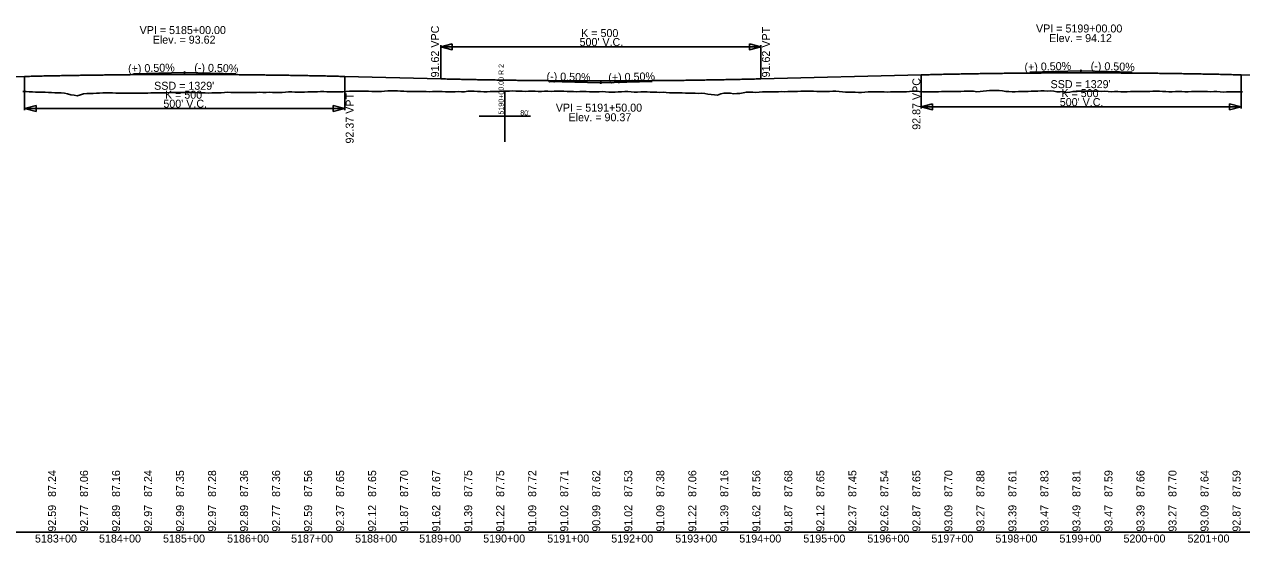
# Model space of a CAD drawing. Extents: x 2147288 to 2220488, y 740833 to 759333.
# Drawn here: x 2150631 to 2152532, y 750067 to 750877 of the extents above; entities that cross this region are included whole.
import ezdxf

# ---------------------------------------------------------------- set-up
doc = ezdxf.new("R2010")
doc.units = 0
for name, color, linetype in [('RD_DDB_GradeTX', 7, 'Continuous'), ('RD_DDB_Profile_EX', 7, 'Continuous'), ('RD_DDB_Profile_Lbl', 7, 'Continuous'), ('RD_DDB_Profile_PR', 7, 'Continuous'), ('RD_DDB_StaTX', 7, 'Continuous'), ('RD_DDB_StripGrade', 7, 'Continuous'), ('RD_DDB_VCLbl', 7, 'Continuous'), ('RD_GPK_Profile_Cell', 7, 'Continuous')]:
    doc.layers.add(name, color=color, linetype=linetype)

msp = doc.modelspace()

# ---------------------------------------------------------------- linework, layer by layer
at = {"layer": 'RD_DDB_GradeTX'}
for p, q in [((2150801.1, 750799.5), (2150880.1, 750801.5)), ((2150961.1, 750799.5), (2150882.1, 750801.5)), ((2152201.1, 750802), (2152280.1, 750804)), ((2152361.1, 750802), (2152282.1, 750804)), ((2151451.1, 750787.3), (2151530.1, 750785.3)), ((2151611.1, 750787.3), (2151532.1, 750785.3))]:
    msp.add_line(p, q, dxfattribs=at)
for centre in [(2150881.1, 750801.5), (2152281.1, 750804), (2151531.1, 750785.3)]:
    msp.add_circle(centre, 1, dxfattribs=at)
at = {"layer": 'RD_DDB_Profile_EX'}
for points in [[(2150628.3, 750771.7), (2150633.3, 750771.6), (2150638.3, 750771.3), (2150643.3, 750771.1), (2150648.3, 750771), (2150653.3, 750770.9), (2150658.3, 750770.7), (2150663.3, 750770.6), (2150668.3, 750770.3), (2150673.3, 750770), (2150678.3, 750769.6), (2150683.3, 750769.7), (2150688.3, 750769.6), (2150693.3, 750769.1), (2150698.3, 750767.9), (2150703.3, 750766.4), (2150708.3, 750765.8), (2150713.3, 750765.1), (2150718.3, 750766.8), (2150723.3, 750768), (2150728.3, 750768.6), (2150733.3, 750768.7), (2150738.3, 750768.9), (2150743.3, 750769.1), (2150748.3, 750769.2), (2150753.3, 750769.5), (2150758.3, 750769.7), (2150763.3, 750769.7), (2150768.3, 750769.6), (2150773.3, 750769.4), (2150778.3, 750769.3), (2150783.3, 750769.2), (2150788.3, 750769.2), (2150793.3, 750769.2), (2150798.3, 750769.3), (2150803.3, 750769.3), (2150808.3, 750769.2), (2150813.3, 750769.4), (2150818.3, 750769.3), (2150823.3, 750769.3), (2150828.3, 750769.5), (2150833.3, 750769.7), (2150838.3, 750769.9), (2150843.3, 750769.8), (2150848.3, 750769.8), (2150853.3, 750769.8), (2150858.3, 750770), (2150863.3, 750770.1), (2150868.3, 750770.2), (2150873.3, 750770.2), (2150878.3, 750770.2), (2150883.3, 750770.2), (2150888.3, 750770.2), (2150893.3, 750770.4), (2150898.3, 750770.1), (2150903.3, 750769.9), (2150908.3, 750769.7), (2150913.3, 750769.5), (2150918.3, 750769.4), (2150923.3, 750769.6), (2150928.3, 750769.9), (2150933.3, 750769.8), (2150938.3, 750769.7), (2150943.3, 750770.2), (2150948.3, 750770.5), (2150953.3, 750770.3), (2150958.3, 750770.3), (2150963.3, 750770.3), (2150968.3, 750770.2), (2150973.3, 750770.2), (2150978.3, 750770.2), (2150983.3, 750770.2), (2150988.3, 750770.3), (2150993.3, 750770.3), (2150998.3, 750770.5), (2151003.3, 750770.2), (2151008.3, 750770.4), (2151013.3, 750770.5), (2151018.3, 750770.4), (2151023.3, 750770.2), (2151028.3, 750770.1), (2151033.3, 750770.3), (2151038.3, 750770.7)], [(2151038.3, 750770.7), (2151043.3, 750771.1), (2151048.3, 750771.3), (2151053.3, 750771), (2151058.3, 750770.7), (2151063.3, 750770.5), (2151068.3, 750770.8), (2151073.3, 750771.1), (2151078.3, 750771.3), (2151083.3, 750771.2), (2151088.3, 750771.4), (2151093.3, 750771.6), (2151098.3, 750771.8), (2151103.3, 750771.5), (2151108.3, 750771.2), (2151113.3, 750771.2), (2151118.3, 750771.2), (2151123.3, 750771.2), (2151128.3, 750771.5), (2151133.3, 750771.8), (2151138.3, 750772.1), (2151143.3, 750772.1), (2151148.3, 750772.2), (2151153.3, 750772.2), (2151158.3, 750772.2), (2151163.3, 750772.2), (2151168.3, 750772.1), (2151173.3, 750771.9), (2151178.3, 750771.7), (2151183.3, 750771.6), (2151188.3, 750771.6), (2151193.3, 750772.2), (2151198.3, 750772.7), (2151203.3, 750772.6), (2151208.3, 750772.6), (2151213.3, 750772.6), (2151218.3, 750772.5), (2151223.3, 750772.3), (2151228.3, 750772), (2151233.3, 750771.9), (2151238.3, 750771.8), (2151243.3, 750771.8), (2151248.3, 750771.7), (2151253.3, 750771.7), (2151258.3, 750771.6), (2151263.3, 750771.5), (2151268.3, 750771.6), (2151273.3, 750771.8), (2151278.3, 750772), (2151283.3, 750771.6), (2151288.3, 750771.3), (2151293.3, 750771.5), (2151298.3, 750771.5), (2151303.3, 750771.3), (2151308.3, 750771.7), (2151313.3, 750771.5), (2151318.3, 750771.3), (2151323.3, 750772.1), (2151328.3, 750772.3), (2151333.3, 750772.1), (2151338.3, 750771.9), (2151343.3, 750771.7), (2151348.3, 750771.5), (2151353.3, 750771.4), (2151358.3, 750771.6), (2151363.3, 750771.7), (2151368.3, 750771.6), (2151373.3, 750771.9), (2151378.3, 750772.2), (2151383.3, 750772.2), (2151388.3, 750772.4), (2151393.3, 750772.6), (2151398.3, 750772.4), (2151403.3, 750772.5), (2151408.3, 750772.3), (2151413.3, 750772), (2151418.3, 750772.1), (2151423.3, 750772.2), (2151428.3, 750772.2), (2151433.3, 750772), (2151438.3, 750772), (2151443.3, 750772.2), (2151448.3, 750772.1), (2151453.3, 750772), (2151458.3, 750772.1), (2151463.3, 750772.1), (2151468.3, 750772.1), (2151473.3, 750772.1), (2151478.3, 750772), (2151483.3, 750771.9), (2151488.3, 750771.7), (2151493.3, 750771.5), (2151498.3, 750771.6), (2151503.3, 750771.7), (2151508.3, 750771.7), (2151513.3, 750771.2), (2151518.3, 750771.4), (2151523.3, 750771.1), (2151528.3, 750771.2), (2151533.3, 750771.8), (2151538.3, 750771.2)], [(2151538.3, 750771.2), (2151543.3, 750770.9), (2151548.3, 750770.9), (2151553.3, 750770.9), (2151558.3, 750771.1), (2151563.3, 750771.5), (2151568.3, 750771.6), (2151573.3, 750771.7), (2151578.3, 750771.2), (2151583.3, 750770.9), (2151588.3, 750771), (2151593.3, 750771.1), (2151598.3, 750771.5), (2151603.3, 750771.1), (2151608.3, 750770.9), (2151613.3, 750770.7), (2151618.3, 750770.5), (2151623.3, 750770.4), (2151628.3, 750770.6), (2151633.3, 750770.1), (2151638.3, 750769.6), (2151643.3, 750769.5), (2151648.3, 750769.6), (2151653.3, 750769.6), (2151658.3, 750769.6), (2151663.3, 750769.3), (2151668.3, 750769.1), (2151673.3, 750769.3), (2151678.3, 750769), (2151683.3, 750768.6), (2151688.3, 750769.2), (2151693.3, 750768.8), (2151698.3, 750767.5), (2151703.3, 750766.9), (2151708.3, 750766.4), (2151713.3, 750766.2), (2151718.3, 750768.4), (2151723.3, 750769.1), (2151728.3, 750769.2), (2151733.3, 750769.2), (2151738.3, 750768.3), (2151743.3, 750768.5), (2151748.3, 750768.9), (2151753.3, 750769.8), (2151758.3, 750770.8), (2151763.3, 750770.7), (2151768.3, 750770.6), (2151773.3, 750770.2), (2151778.3, 750770.9), (2151783.3, 750771.4), (2151788.3, 750771.3), (2151793.3, 750771.3), (2151798.3, 750771.3), (2151803.3, 750771.2), (2151808.3, 750771.2), (2151813.3, 750771.6), (2151818.3, 750771.5), (2151823.3, 750771.7), (2151828.3, 750771.8), (2151833.3, 750771.9), (2151838.3, 750772), (2151843.3, 750772.4), (2151848.3, 750772.3), (2151853.3, 750772.1), (2151858.3, 750772.3), (2151863.3, 750772.1), (2151868.3, 750771.9), (2151873.3, 750771.8), (2151878.3, 750771.6), (2151883.3, 750771.7), (2151888.3, 750771.9), (2151893.3, 750772.1), (2151898.3, 750772.3), (2151903.3, 750771.7), (2151908.3, 750771.1), (2151913.3, 750770.7), (2151918.3, 750770.6), (2151923.3, 750770.9), (2151928.3, 750771), (2151933.3, 750770.4), (2151938.3, 750770.3), (2151943.3, 750770.7), (2151948.3, 750771.1), (2151953.3, 750771.4), (2151958.3, 750771.3), (2151963.3, 750771.3), (2151968.3, 750771.2), (2151973.3, 750771.2), (2151978.3, 750771), (2151983.3, 750771.3), (2151988.3, 750771.1), (2151993.3, 750771.1), (2151998.3, 750771.3), (2152003.3, 750771.5), (2152008.3, 750771.5), (2152013.3, 750771.9), (2152018.3, 750772.5), (2152023.3, 750772.2), (2152028.3, 750771.9), (2152033.3, 750771.5), (2152038.3, 750771.3)], [(2152038.3, 750771.3), (2152043.3, 750771.2), (2152048.3, 750771.3), (2152053.3, 750771.4), (2152058.3, 750771.5), (2152063.3, 750771.6), (2152068.3, 750771.7), (2152073.3, 750771.8), (2152078.3, 750771.9), (2152083.3, 750772), (2152088.3, 750771.9), (2152093.3, 750771.9), (2152098.3, 750772.1), (2152103.3, 750772.4), (2152108.3, 750772.5), (2152113.3, 750772.1), (2152118.3, 750771.5), (2152123.3, 750771.9), (2152128.3, 750772.5), (2152133.3, 750773), (2152138.3, 750773.3), (2152143.3, 750773.6), (2152148.3, 750773.4), (2152153.3, 750773.1), (2152158.3, 750772.8), (2152163.3, 750772), (2152168.3, 750771.6), (2152173.3, 750771.2), (2152178.3, 750771.4), (2152183.3, 750771.6), (2152188.3, 750771.6), (2152193.3, 750771.7), (2152198.3, 750771.8), (2152203.3, 750772.1), (2152208.3, 750772.3), (2152213.3, 750772.3), (2152218.3, 750772.6), (2152223.3, 750772.7), (2152228.3, 750772.5), (2152233.3, 750772.7), (2152238.3, 750772.2), (2152243.3, 750771.3), (2152248.3, 750771.2), (2152253.3, 750771.7), (2152258.3, 750770.4), (2152263.3, 750770.8), (2152268.3, 750771.7), (2152273.3, 750772.1), (2152278.3, 750772.4), (2152283.3, 750772.5), (2152288.3, 750772.3), (2152293.3, 750772.5), (2152298.3, 750772.4), (2152303.3, 750772.4), (2152308.3, 750772.2), (2152313.3, 750772), (2152318.3, 750772.1), (2152323.3, 750771.9), (2152328.3, 750771.2), (2152333.3, 750771.6), (2152338.3, 750772), (2152343.3, 750771.3), (2152348.3, 750771.1), (2152353.3, 750771.5), (2152358.3, 750772), (2152363.3, 750771.8), (2152368.3, 750771.8), (2152373.3, 750771.8), (2152378.3, 750771.6), (2152383.3, 750771.8), (2152388.3, 750772), (2152393.3, 750772.2), (2152398.3, 750772.3), (2152403.3, 750772.3), (2152408.3, 750772), (2152413.3, 750771.7), (2152418.3, 750771.5), (2152423.3, 750771.3), (2152428.3, 750771.8), (2152433.3, 750772), (2152438.3, 750771.7), (2152443.3, 750771.5), (2152448.3, 750771.5), (2152453.3, 750771.6), (2152458.3, 750771.7), (2152463.3, 750771.6), (2152468.3, 750771.8), (2152473.3, 750772), (2152478.3, 750771.7), (2152483.3, 750771.5), (2152488.3, 750771.6), (2152493.3, 750771.6), (2152498.3, 750771.3), (2152503.3, 750771), (2152508.3, 750771.2), (2152513.3, 750771.4), (2152518.3, 750771.5), (2152523.3, 750771.5), (2152528.3, 750771.4), (2152533.3, 750771.3)]]:
    msp.add_lwpolyline(points, dxfattribs=at)
at = {"layer": 'RD_DDB_Profile_PR'}
for p, q in [((2151781.1, 750791.5), (2152031.1, 750797.8)), ((2152531.1, 750797.8), (2152781.1, 750791.5)), ((2150481.1, 750791.5), (2150631.1, 750795.3)), ((2151131.1, 750795.3), (2151281.1, 750791.5))]:
    msp.add_line(p, q, dxfattribs=at)
for points in [[(2150631.1, 750795.3), (2150641.1, 750795.5), (2150651.1, 750795.7), (2150661.1, 750796), (2150671.1, 750796.2), (2150681.1, 750796.4), (2150691.1, 750796.6), (2150701.1, 750796.8), (2150711.1, 750796.9), (2150721.1, 750797.1), (2150731.1, 750797.3), (2150741.1, 750797.4), (2150751.1, 750797.5), (2150761.1, 750797.7), (2150771.1, 750797.8), (2150781.1, 750797.9), (2150791.1, 750798), (2150801.1, 750798.1), (2150811.1, 750798.1), (2150821.1, 750798.2), (2150831.1, 750798.3), (2150841.1, 750798.3), (2150851.1, 750798.3), (2150861.1, 750798.4), (2150871.1, 750798.4), (2150881.1, 750798.4), (2150891.1, 750798.4), (2150901.1, 750798.4), (2150911.1, 750798.3), (2150921.1, 750798.3), (2150931.1, 750798.3), (2150941.1, 750798.2), (2150951.1, 750798.1), (2150961.1, 750798.1), (2150971.1, 750798), (2150981.1, 750797.9), (2150991.1, 750797.8), (2151001.1, 750797.7), (2151011.1, 750797.5), (2151021.1, 750797.4), (2151031.1, 750797.3), (2151041.1, 750797.1), (2151051.1, 750796.9), (2151061.1, 750796.8), (2151071.1, 750796.6), (2151081.1, 750796.4), (2151091.1, 750796.2), (2151101.1, 750796), (2151111.1, 750795.7), (2151121.1, 750795.5), (2151131.1, 750795.3)], [(2152031.1, 750797.8), (2152041.1, 750798), (2152051.1, 750798.2), (2152061.1, 750798.5), (2152071.1, 750798.7), (2152081.1, 750798.9), (2152091.1, 750799.1), (2152101.1, 750799.3), (2152111.1, 750799.4), (2152121.1, 750799.6), (2152131.1, 750799.8), (2152141.1, 750799.9), (2152151.1, 750800), (2152161.1, 750800.2), (2152171.1, 750800.3), (2152181.1, 750800.4), (2152191.1, 750800.5), (2152201.1, 750800.6), (2152211.1, 750800.6), (2152221.1, 750800.7), (2152231.1, 750800.8), (2152241.1, 750800.8), (2152251.1, 750800.8), (2152261.1, 750800.9), (2152271.1, 750800.9), (2152281.1, 750800.9), (2152291.1, 750800.9), (2152301.1, 750800.9), (2152311.1, 750800.8), (2152321.1, 750800.8), (2152331.1, 750800.8), (2152341.1, 750800.7), (2152351.1, 750800.6), (2152361.1, 750800.6), (2152371.1, 750800.5), (2152381.1, 750800.4), (2152391.1, 750800.3), (2152401.1, 750800.2), (2152411.1, 750800), (2152421.1, 750799.9), (2152431.1, 750799.8), (2152441.1, 750799.6), (2152451.1, 750799.4), (2152461.1, 750799.3), (2152471.1, 750799.1), (2152481.1, 750798.9), (2152491.1, 750798.7), (2152501.1, 750798.5), (2152511.1, 750798.2), (2152521.1, 750798), (2152531.1, 750797.8)], [(2151281.1, 750791.5), (2151291.1, 750791.3), (2151301.1, 750791), (2151311.1, 750790.8), (2151321.1, 750790.6), (2151331.1, 750790.4), (2151341.1, 750790.2), (2151351.1, 750790), (2151361.1, 750789.8), (2151371.1, 750789.7), (2151381.1, 750789.5), (2151391.1, 750789.4), (2151401.1, 750789.2), (2151411.1, 750789.1), (2151421.1, 750789), (2151431.1, 750788.9), (2151441.1, 750788.8), (2151451.1, 750788.7), (2151461.1, 750788.6), (2151471.1, 750788.6), (2151481.1, 750788.5), (2151491.1, 750788.5), (2151501.1, 750788.4), (2151511.1, 750788.4), (2151521.1, 750788.4), (2151531.1, 750788.4), (2151541.1, 750788.4), (2151551.1, 750788.4), (2151561.1, 750788.4), (2151571.1, 750788.5), (2151581.1, 750788.5), (2151591.1, 750788.6), (2151601.1, 750788.6), (2151611.1, 750788.7), (2151621.1, 750788.8), (2151631.1, 750788.9), (2151641.1, 750789), (2151651.1, 750789.1), (2151661.1, 750789.2), (2151671.1, 750789.4), (2151681.1, 750789.5), (2151691.1, 750789.7), (2151701.1, 750789.8), (2151711.1, 750790), (2151721.1, 750790.2), (2151731.1, 750790.4), (2151741.1, 750790.6), (2151751.1, 750790.8), (2151761.1, 750791), (2151771.1, 750791.3), (2151781.1, 750791.5)]]:
    msp.add_spline(points, degree=3, dxfattribs=at)
at = {"layer": 'RD_DDB_VCLbl'}
for p, q in [((2151281.1, 750844), (2151281.1, 750791.5)), ((2151281.1, 750841.5), (2151781.1, 750841.5)), ((2151781.1, 750844), (2151781.1, 750791.5)), ((2152031.1, 750745.3), (2152031.1, 750797.8)), ((2152531.1, 750745.3), (2152531.1, 750797.8)), ((2150631.1, 750742.8), (2150631.1, 750795.3)), ((2151131.1, 750742.8), (2151131.1, 750795.3)), ((2150631.1, 750745.3), (2151131.1, 750745.3)), ((2152031.1, 750747.8), (2152531.1, 750747.8))]:
    msp.add_line(p, q, dxfattribs=at)
for points in [[(2151299.1, 750846), (2151281.1, 750841.5), (2151299.1, 750837)], [(2151763.1, 750846), (2151781.1, 750841.5), (2151763.1, 750837)], [(2150649.1, 750749.8), (2150631.1, 750745.3), (2150649.1, 750740.8)], [(2151113.1, 750749.8), (2151131.1, 750745.3), (2151113.1, 750740.8)], [(2152049.1, 750752.3), (2152031.1, 750747.8), (2152049.1, 750743.3)], [(2152513.1, 750752.3), (2152531.1, 750747.8), (2152513.1, 750743.3)]]:
    msp.add_lwpolyline(points, close=True, dxfattribs=at)
at = {"layer": 'RD_GPK_Profile_Cell'}
for p, q in [((2151381.1, 750773.4), (2151381.1, 750693.4)), ((2151421.1, 750733.4), (2151341.1, 750733.4)), ((2148888.3, 750083.4), (2170488.3, 750083.4))]:
    msp.add_line(p, q, dxfattribs=at)

# ---------------------------------------------------------------- texts
at = {"layer": 'RD_DDB_GradeTX'}
for s, rotation, p in [('(+) 0.50%', 1.4321, (2152192.8, 750803.8)), ('(-) 0.50%', 358.5679, (2152296, 750805.6)), ('(+) 0.50%', 1.4321, (2150792.8, 750801.3)), ('(-) 0.50%', 358.5679, (2150896, 750803.1)), ('(-) 0.50%', 358.5679, (2151446.1, 750789.4)), ('(+) 0.50%', 1.4321, (2151542.8, 750787.6))]:
    msp.add_text(s, height=12.5, rotation=rotation, dxfattribs=at).set_placement(p)
at = {"layer": 'RD_DDB_Profile_Lbl'}
for s, p in [('VPI = 5185+00.00', (2150810.7, 750861.5)), ('VPI = 5199+00.00', (2152210.7, 750864)), ('Elev. = 93.62', (2150831.2, 750846.5)), ('Elev. = 94.12', (2152231.2, 750849)), ('VPI = 5191+50.00', (2151460.7, 750740.3)), ('Elev. = 90.37', (2151480.6, 750725.3))]:
    msp.add_text(s, height=12.5, dxfattribs=at).set_placement(p)
at = {"layer": 'RD_DDB_StaTX'}
for s, p in [('5183+00', (2150647.3, 750067.2)), ('5184+00', (2150747.3, 750067.2)), ('5185+00', (2150847.3, 750067.2)), ('5186+00', (2150947.3, 750067.2)), ('5187+00', (2151047.3, 750067.2)), ('5188+00', (2151147.3, 750067.2)), ('5189+00', (2151247.3, 750067.2)), ('5190+00', (2151347.3, 750067.2)), ('5191+00', (2151447.3, 750067.2)), ('5192+00', (2151547.3, 750067.2)), ('5193+00', (2151647.3, 750067.2)), ('5194+00', (2151747.3, 750067.2)), ('5195+00', (2151847.3, 750067.2)), ('5196+00', (2151947.3, 750067.2)), ('5197+00', (2152047.3, 750067.2)), ('5198+00', (2152147.3, 750067.2)), ('5199+00', (2152247.3, 750067.2)), ('5200+00', (2152347.3, 750067.2)), ('5201+00', (2152447.3, 750067.2))]:
    msp.add_text(s, height=12.5, dxfattribs=at).set_placement(p)
at = {"layer": 'RD_DDB_StripGrade'}
for s, p in [('91.62 VPC', (2151278.3, 750793.8)), ('91.62 VPT', (2151795.2, 750793.8)), ('92.87 VPC', (2152030.1, 750712)), ('92.37 VPT', (2151145, 750690.5)), ('87.24', (2150680.1, 750138.4)), ('87.06', (2150730.1, 750138.4)), ('87.16', (2150780.1, 750138.4)), ('87.24', (2150830.1, 750138.4)), ('87.35', (2150880.1, 750138.4)), ('87.28', (2150930.1, 750138.4)), ('87.36', (2150980.1, 750138.4)), ('87.36', (2151030.1, 750138.4)), ('87.56', (2151080.1, 750138.4)), ('87.65', (2151130.1, 750138.4)), ('87.65', (2151180.1, 750138.4)), ('87.70', (2151230.1, 750138.4)), ('87.67', (2151280.1, 750138.4)), ('87.75', (2151330.1, 750138.4)), ('87.75', (2151380.1, 750138.4)), ('87.72', (2151430.1, 750138.4)), ('87.71', (2151480.1, 750138.4)), ('87.62', (2151530.1, 750138.4)), ('87.53', (2151580.1, 750138.4)), ('87.38', (2151630.1, 750138.4)), ('87.06', (2151680.1, 750138.4)), ('87.16', (2151730.1, 750138.4)), ('87.56', (2151780.1, 750138.4)), ('87.68', (2151830.1, 750138.4)), ('87.65', (2151880.1, 750138.4)), ('87.45', (2151930.1, 750138.4)), ('87.54', (2151980.1, 750138.4)), ('87.65', (2152030.1, 750138.4)), ('87.70', (2152080.1, 750138.4)), ('87.88', (2152130.1, 750138.4)), ('87.61', (2152180.1, 750138.4)), ('87.83', (2152230.1, 750138.4)), ('87.81', (2152280.1, 750138.4)), ('87.59', (2152330.1, 750138.4)), ('87.66', (2152380.1, 750138.4)), ('87.70', (2152430.1, 750138.4)), ('87.64', (2152480.1, 750138.4)), ('87.59', (2152530.1, 750138.4)), ('92.59', (2150680.1, 750084.2)), ('92.77', (2150730.1, 750084.2)), ('92.89', (2150780.1, 750084.2)), ('92.97', (2150830.1, 750084.2)), ('92.99', (2150880.1, 750084.2)), ('92.97', (2150930.1, 750084.2)), ('92.89', (2150980.1, 750084.2)), ('92.77', (2151030.1, 750084.2)), ('92.59', (2151080.1, 750084.2)), ('92.37', (2151130.1, 750084.2)), ('92.12', (2151180.1, 750084.2)), ('91.87', (2151230.1, 750084.2)), ('91.62', (2151280.1, 750084.2)), ('91.39', (2151330.1, 750084.2)), ('91.22', (2151380.1, 750084.2)), ('91.09', (2151430.1, 750084.2)), ('91.02', (2151480.1, 750084.2)), ('90.99', (2151530.1, 750084.2)), ('91.02', (2151580.1, 750084.2)), ('91.09', (2151630.1, 750084.2)), ('91.22', (2151680.1, 750084.2)), ('91.39', (2151730.1, 750084.2)), ('91.62', (2151780.1, 750084.2)), ('91.87', (2151830.1, 750084.2)), ('92.12', (2151880.1, 750084.2)), ('92.37', (2151930.1, 750084.2)), ('92.62', (2151980.1, 750084.2)), ('92.87', (2152030.1, 750084.2)), ('93.09', (2152080.1, 750084.2)), ('93.27', (2152130.1, 750084.2)), ('93.39', (2152180.1, 750084.2)), ('93.47', (2152230.1, 750084.2)), ('93.49', (2152280.1, 750084.2)), ('93.47', (2152330.1, 750084.2)), ('93.39', (2152380.1, 750084.2)), ('93.27', (2152430.1, 750084.2)), ('93.09', (2152480.1, 750084.2)), ('92.87', (2152530.1, 750084.2))]:
    msp.add_text(s, height=12.5, rotation=90, dxfattribs=at).set_placement(p)
at = {"layer": 'RD_DDB_VCLbl'}
for s, p in [("500' V.C.", (2151497.8, 750842.8)), ('K = 500', (2151500.3, 750856.8)), ("SSD = 1329'", (2150833.4, 750774.5)), ("SSD = 1329'", (2152233.4, 750777)), ('K = 500', (2150850.3, 750760.5)), ("500' V.C.", (2152247.8, 750749)), ('K = 500', (2152250.3, 750763)), ("500' V.C.", (2150847.8, 750746.5))]:
    msp.add_text(s, height=12.5, dxfattribs=at).set_placement(p)
at = {"layer": 'RD_GPK_Profile_Cell'}
msp.add_text('5190+00.00 R 2', height=8, rotation=90, dxfattribs=at).set_placement((2151379.3, 750735.8))
msp.add_text("80'", height=8, dxfattribs=at).set_placement((2151405.2, 750734.6))

doc.saveas('drawing.dxf')
